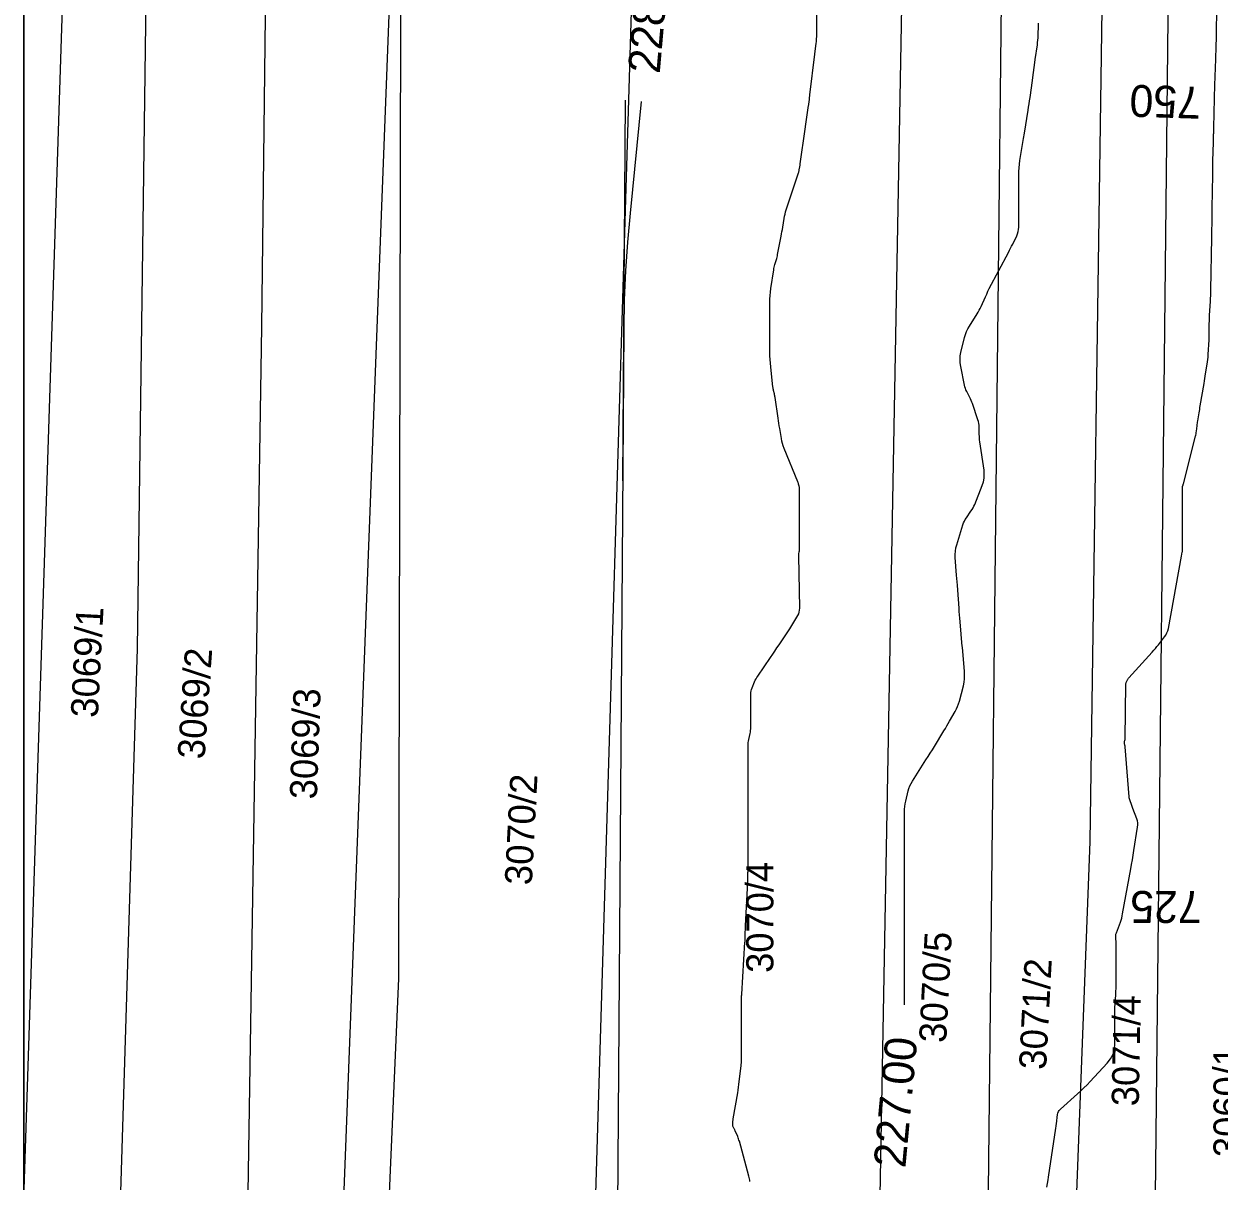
# Model space of a CAD drawing. Extents: x -534410 to -534262, y -1190162 to -1189584.
# Drawn here: x -534410.13 to -534372.7, y -1189864.58 to -1189828.34 of the extents above; entities that cross this region are included whole.
import ezdxf

# ---------------------------------------------------------------- set-up
doc = ezdxf.new("R2010")
doc.units = 0
for name, color, linetype in [('30', 7, 'Continuous'), ('31', 7, 'Continuous'), ('40', 7, 'Continuous'), ('_N_text', 7, 'Continuous'), ('_rámeček', 7, 'Continuous'), ('_rámeček_mřížka', 7, 'Continuous'), ('Hranice parcel', 7, 'Continuous'), ('Parcelní čísla', 7, 'Continuous')]:
    doc.layers.add(name, color=color, linetype=linetype)

msp = doc.modelspace()

# ---------------------------------------------------------------- linework, layer by layer
at = {"layer": '30'}
for points in [[(-534382.549, -1189859.059), (-534382.549, -1189853.012), (-534382.547, -1189852.928), (-534382.54, -1189852.846), (-534382.527, -1189852.764), (-534382.51, -1189852.682), (-534382.432, -1189852.357), (-534382.409, -1189852.278), (-534382.38, -1189852.2), (-534382.345, -1189852.126), (-534382.303, -1189852.054), (-534381.877, -1189851.384), (-534381.81, -1189851.279), (-534381.744, -1189851.173), (-534381.678, -1189851.068), (-534381.613, -1189850.961), (-534381.314, -1189850.474), (-534381.269, -1189850.399), (-534381.224, -1189850.323), (-534381.179, -1189850.247), (-534381.136, -1189850.171), (-534380.961, -1189849.866), (-534380.921, -1189849.788), (-534380.885, -1189849.709), (-534380.855, -1189849.627), (-534380.831, -1189849.543), (-534380.707, -1189849.062), (-534380.684, -1189848.953), (-534380.67, -1189848.843), (-534380.666, -1189848.732), (-534380.671, -1189848.621), (-534380.738, -1189847.85), (-534380.739, -1189847.838), (-534380.807, -1189847.058), (-534380.816, -1189846.951), (-534380.825, -1189846.844), (-534380.834, -1189846.738), (-534380.842, -1189846.631), (-534380.883, -1189846.069), (-534380.895, -1189845.912), (-534380.918, -1189845.597), (-534380.958, -1189845.052), (-534380.961, -1189844.949), (-534380.954, -1189844.847), (-534380.938, -1189844.745), (-534380.912, -1189844.645), (-534380.721, -1189844.021), (-534380.701, -1189843.963), (-534380.676, -1189843.907), (-534380.647, -1189843.853), (-534380.613, -1189843.802), (-534380.469, -1189843.6), (-534380.435, -1189843.548), (-534380.404, -1189843.495), (-534380.376, -1189843.44), (-534380.351, -1189843.383), (-534380.117, -1189842.797), (-534380.079, -1189842.679), (-534380.056, -1189842.56), (-534380.05, -1189842.438), (-534380.06, -1189842.314), (-534380.189, -1189841.421), (-534380.196, -1189841.364), (-534380.202, -1189841.306), (-534380.206, -1189841.249), (-534380.208, -1189841.191), (-534380.213, -1189840.96), (-534380.216, -1189840.903), (-534380.224, -1189840.846), (-534380.236, -1189840.79), (-534380.252, -1189840.735), (-534380.425, -1189840.228), (-534380.443, -1189840.178), (-534380.463, -1189840.13), (-534380.484, -1189840.082), (-534380.507, -1189840.034), (-534380.603, -1189839.846), (-534380.625, -1189839.799), (-534380.644, -1189839.75), (-534380.66, -1189839.7), (-534380.672, -1189839.649), (-534380.79, -1189839.066), (-534380.806, -1189838.955), (-534380.81, -1189838.845), (-534380.802, -1189838.735), (-534380.782, -1189838.625), (-534380.669, -1189838.154), (-534380.642, -1189838.061), (-534380.608, -1189837.971), (-534380.567, -1189837.884), (-534380.518, -1189837.8), (-534380.273, -1189837.414), (-534380.24, -1189837.36), (-534380.209, -1189837.305), (-534380.179, -1189837.248), (-534380.151, -1189837.191), (-534380.011, -1189836.888), (-534380.001, -1189836.866), (-534379.991, -1189836.844), (-534379.982, -1189836.822), (-534379.973, -1189836.8), (-534379.938, -1189836.711), (-534379.929, -1189836.689), (-534379.92, -1189836.667), (-534379.909, -1189836.646), (-534379.898, -1189836.625), (-534379.293, -1189835.49), (-534379.259, -1189835.426), (-534379.226, -1189835.362), (-534379.194, -1189835.298), (-534379.162, -1189835.233), (-534379.036, -1189834.974), (-534379.008, -1189834.908), (-534378.989, -1189834.841), (-534378.977, -1189834.772), (-534378.973, -1189834.7), (-534378.973, -1189833.078), (-534378.971, -1189832.961), (-534378.964, -1189832.845), (-534378.952, -1189832.73), (-534378.935, -1189832.614), (-534378.822, -1189831.924), (-534378.794, -1189831.754), (-534378.678, -1189831.042), (-534378.662, -1189830.943), (-534378.647, -1189830.844), (-534378.632, -1189830.745), (-534378.618, -1189830.646), (-534378.544, -1189830.112), (-534378.52, -1189829.931), (-534378.478, -1189829.631), (-534378.453, -1189829.451), (-534378.39, -1189828.995), (-534378.381, -1189828.919), (-534378.374, -1189828.844), (-534378.368, -1189828.769), (-534378.364, -1189828.693), (-534378.354, -1189828.39), (-534378.352, -1189828.315)], [(-534390.792, -1189830.764), (-534391.145, -1189834.263), (-534391.226, -1189835.167), (-534391.285, -1189836.071), (-534391.324, -1189836.977), (-534391.341, -1189837.885), (-534391.562, -1189868.34)]]:
    msp.add_lwpolyline(points, dxfattribs=at)
at = {"layer": '31'}
for points in [[(-534387.392, -1189864.586), (-534387.396, -1189864.543), (-534387.403, -1189864.501), (-534387.411, -1189864.459), (-534387.422, -1189864.417), (-534387.722, -1189863.328), (-534387.733, -1189863.291), (-534387.746, -1189863.254), (-534387.759, -1189863.217), (-534387.774, -1189863.182), (-534387.852, -1189862.999), (-534387.859, -1189862.984), (-534387.867, -1189862.968), (-534387.874, -1189862.952), (-534387.882, -1189862.937), (-534387.915, -1189862.875), (-534387.922, -1189862.86), (-534387.927, -1189862.844), (-534387.929, -1189862.827), (-534387.929, -1189862.81), (-534387.922, -1189862.712), (-534387.921, -1189862.69), (-534387.918, -1189862.668), (-534387.915, -1189862.646), (-534387.912, -1189862.625), (-534387.773, -1189861.813), (-534387.759, -1189861.724), (-534387.746, -1189861.636), (-534387.734, -1189861.548), (-534387.723, -1189861.459), (-534387.666, -1189860.969), (-534387.664, -1189860.948), (-534387.662, -1189860.926), (-534387.66, -1189860.904), (-534387.659, -1189860.883), (-534387.654, -1189860.796), (-534387.653, -1189860.774), (-534387.652, -1189860.753), (-534387.652, -1189860.731), (-534387.651, -1189860.709), (-534387.651, -1189858.867), (-534387.651, -1189858.856), (-534387.651, -1189858.845), (-534387.651, -1189858.833), (-534387.651, -1189858.822), (-534387.649, -1189858.773), (-534387.649, -1189858.762), (-534387.648, -1189858.75), (-534387.648, -1189858.738), (-534387.647, -1189858.726), (-534387.545, -1189857.096), (-534387.544, -1189857.071), (-534387.542, -1189857.045), (-534387.541, -1189857.02), (-534387.541, -1189856.995), (-534387.537, -1189856.895), (-534387.536, -1189856.844), (-534387.535, -1189856.794), (-534387.532, -1189856.685), (-534387.531, -1189856.659), (-534387.53, -1189856.632), (-534387.529, -1189856.605), (-534387.528, -1189856.579), (-534387.46, -1189855.203), (-534387.458, -1189855.167), (-534387.457, -1189855.131), (-534387.456, -1189855.095), (-534387.455, -1189855.06), (-534387.451, -1189854.916), (-534387.45, -1189854.88), (-534387.45, -1189854.844), (-534387.45, -1189854.809), (-534387.449, -1189854.773), (-534387.449, -1189850.942), (-534387.448, -1189850.893), (-534387.444, -1189850.845), (-534387.437, -1189850.797), (-534387.428, -1189850.749), (-534387.385, -1189850.559), (-534387.375, -1189850.512), (-534387.368, -1189850.464), (-534387.364, -1189850.415), (-534387.363, -1189850.367), (-534387.363, -1189849.328), (-534387.36, -1189849.277), (-534387.353, -1189849.227), (-534387.34, -1189849.178), (-534387.323, -1189849.13), (-534387.243, -1189848.94), (-534387.222, -1189848.893), (-534387.199, -1189848.847), (-534387.173, -1189848.803), (-534387.145, -1189848.759), (-534386.746, -1189848.177), (-534386.678, -1189848.077), (-534386.61, -1189847.978), (-534386.543, -1189847.878), (-534386.476, -1189847.778), (-534386.142, -1189847.277), (-534386.109, -1189847.226), (-534386.076, -1189847.175), (-534386.045, -1189847.124), (-534386.013, -1189847.072), (-534385.89, -1189846.863), (-534385.864, -1189846.81), (-534385.845, -1189846.755), (-534385.834, -1189846.697), (-534385.831, -1189846.638), (-534385.861, -1189844.993), (-534385.861, -1189844.978), (-534385.86, -1189844.963), (-534385.859, -1189844.948), (-534385.857, -1189844.933), (-534385.846, -1189844.874), (-534385.844, -1189844.859), (-534385.842, -1189844.844), (-534385.842, -1189844.829), (-534385.841, -1189844.814), (-534385.841, -1189842.879), (-534385.842, -1189842.862), (-534385.843, -1189842.845), (-534385.846, -1189842.828), (-534385.85, -1189842.812), (-534385.867, -1189842.746), (-534385.871, -1189842.729), (-534385.876, -1189842.713), (-534385.882, -1189842.697), (-534385.888, -1189842.681), (-534386.317, -1189841.629), (-534386.345, -1189841.553), (-534386.37, -1189841.477), (-534386.389, -1189841.4), (-534386.405, -1189841.321), (-534386.459, -1189841.003), (-534386.472, -1189840.924), (-534386.485, -1189840.844), (-534386.497, -1189840.765), (-534386.508, -1189840.685), (-534386.601, -1189840.033), (-534386.606, -1189840.006), (-534386.611, -1189839.979), (-534386.616, -1189839.952), (-534386.622, -1189839.925), (-534386.649, -1189839.818), (-534386.656, -1189839.791), (-534386.661, -1189839.764), (-534386.665, -1189839.737), (-534386.669, -1189839.709), (-534386.739, -1189839.074), (-534386.75, -1189838.959), (-534386.758, -1189838.844), (-534386.763, -1189838.729), (-534386.765, -1189838.613), (-534386.765, -1189838.111), (-534386.765, -1189837.866), (-534386.765, -1189837.621), (-534386.765, -1189837.069), (-534386.763, -1189836.957), (-534386.756, -1189836.845), (-534386.746, -1189836.733), (-534386.732, -1189836.622), (-534386.645, -1189836.036), (-534386.638, -1189835.996), (-534386.63, -1189835.956), (-534386.62, -1189835.916), (-534386.609, -1189835.876), (-534386.562, -1189835.719), (-534386.551, -1189835.68), (-534386.541, -1189835.64), (-534386.532, -1189835.6), (-534386.524, -1189835.56), (-534386.412, -1189834.982), (-534386.399, -1189834.913), (-534386.387, -1189834.844), (-534386.375, -1189834.775), (-534386.363, -1189834.706), (-534386.318, -1189834.43), (-534386.306, -1189834.361), (-534386.291, -1189834.293), (-534386.273, -1189834.226), (-534386.252, -1189834.159), (-534385.87, -1189833.002), (-534385.863, -1189832.979), (-534385.857, -1189832.956), (-534385.851, -1189832.933), (-534385.847, -1189832.909), (-534385.83, -1189832.814), (-534385.826, -1189832.79), (-534385.822, -1189832.766), (-534385.818, -1189832.742), (-534385.815, -1189832.718), (-534385.763, -1189832.348), (-534385.753, -1189832.278), (-534385.743, -1189832.209), (-534385.733, -1189832.139), (-534385.723, -1189832.069), (-534385.573, -1189831.039), (-534385.551, -1189830.888), (-534385.548, -1189830.866), (-534385.545, -1189830.844), (-534385.542, -1189830.823), (-534385.54, -1189830.801), (-534385.51, -1189830.562), (-534385.354, -1189829.289), (-534385.312, -1189828.943), (-534385.307, -1189828.894), (-534385.303, -1189828.844), (-534385.301, -1189828.795), (-534385.3, -1189828.745), (-534385.3, -1189820.955)], [(-534378.088, -1189864.767), (-534378.053, -1189864.535), (-534378.041, -1189864.457), (-534377.811, -1189862.919), (-534377.802, -1189862.857), (-534377.799, -1189862.838), (-534377.792, -1189862.782), (-534377.756, -1189862.493), (-534377.745, -1189862.445), (-534377.727, -1189862.401), (-534377.702, -1189862.361), (-534377.668, -1189862.326), (-534377.131, -1189861.844), (-534377.03, -1189861.751), (-534376.931, -1189861.656), (-534376.834, -1189861.559), (-534376.74, -1189861.46), (-534376.201, -1189860.886), (-534376.095, -1189860.751), (-534376.02, -1189860.604), (-534375.974, -1189860.445), (-534375.959, -1189860.275), (-534375.959, -1189859.161), (-534375.959, -1189859.111), (-534375.957, -1189859.061), (-534375.955, -1189859.011), (-534375.951, -1189858.961), (-534375.935, -1189858.761), (-534375.931, -1189858.711), (-534375.928, -1189858.661), (-534375.927, -1189858.611), (-534375.926, -1189858.561), (-534375.926, -1189857.074), (-534375.926, -1189857.051), (-534375.927, -1189857.028), (-534375.927, -1189857.005), (-534375.928, -1189856.982), (-534375.931, -1189856.89), (-534375.93, -1189856.868), (-534375.928, -1189856.845), (-534375.923, -1189856.823), (-534375.916, -1189856.802), (-534375.79, -1189856.466), (-534375.768, -1189856.402), (-534375.749, -1189856.338), (-534375.733, -1189856.273), (-534375.719, -1189856.207), (-534375.464, -1189854.801), (-534375.439, -1189854.657), (-534375.414, -1189854.513), (-534375.39, -1189854.369), (-534375.367, -1189854.224), (-534375.252, -1189853.491), (-534375.246, -1189853.424), (-534375.248, -1189853.358), (-534375.258, -1189853.293), (-534375.277, -1189853.229), (-534375.395, -1189852.904), (-534375.406, -1189852.874), (-534375.417, -1189852.845), (-534375.428, -1189852.815), (-534375.439, -1189852.786), (-534375.485, -1189852.668), (-534375.496, -1189852.639), (-534375.504, -1189852.609), (-534375.51, -1189852.578), (-534375.513, -1189852.547), (-534375.639, -1189850.973), (-534375.64, -1189850.96), (-534375.642, -1189850.947), (-534375.645, -1189850.934), (-534375.648, -1189850.921), (-534375.66, -1189850.87), (-534375.663, -1189850.857), (-534375.663, -1189850.845), (-534375.662, -1189850.832), (-534375.66, -1189850.819), (-534375.646, -1189850.767), (-534375.643, -1189850.754), (-534375.641, -1189850.74), (-534375.64, -1189850.727), (-534375.639, -1189850.714), (-534375.615, -1189849.009), (-534375.614, -1189848.991), (-534375.61, -1189848.974), (-534375.605, -1189848.957), (-534375.598, -1189848.941), (-534375.564, -1189848.877), (-534375.555, -1189848.861), (-534375.545, -1189848.846), (-534375.534, -1189848.831), (-534375.522, -1189848.818), (-534374.792, -1189848.011), (-534374.741, -1189847.954), (-534374.692, -1189847.896), (-534374.643, -1189847.837), (-534374.596, -1189847.778), (-534374.408, -1189847.536), (-534374.366, -1189847.474), (-534374.331, -1189847.408), (-534374.305, -1189847.339), (-534374.287, -1189847.266), (-534373.874, -1189845.001), (-534373.863, -1189844.939), (-534373.851, -1189844.876), (-534373.849, -1189844.86), (-534373.847, -1189844.844), (-534373.846, -1189844.829), (-534373.845, -1189844.813), (-534373.845, -1189842.865), (-534373.845, -1189842.855), (-534373.844, -1189842.845), (-534373.842, -1189842.834), (-534373.84, -1189842.824), (-534373.826, -1189842.774), (-534373.821, -1189842.754), (-534373.818, -1189842.744), (-534373.436, -1189841.252), (-534373.426, -1189841.212), (-534373.418, -1189841.172), (-534373.411, -1189841.131), (-534373.406, -1189841.09), (-534373.387, -1189840.926), (-534373.382, -1189840.886), (-534373.377, -1189840.845), (-534373.371, -1189840.804), (-534373.365, -1189840.763), (-534373.324, -1189840.517), (-534373.315, -1189840.462), (-534373.306, -1189840.408), (-534373.297, -1189840.353), (-534373.288, -1189840.298), (-534373.169, -1189839.594), (-534373.156, -1189839.519), (-534373.144, -1189839.444), (-534373.131, -1189839.369), (-534373.119, -1189839.294), (-534373.071, -1189838.994), (-534373.059, -1189838.919), (-534373.05, -1189838.844), (-534373.043, -1189838.769), (-534373.038, -1189838.693), (-534373.011, -1189838.235), (-534373.008, -1189838.17), (-534373.006, -1189838.105), (-534373.004, -1189838.04), (-534373.004, -1189837.975), (-534373.004, -1189837.714), (-534373.003, -1189837.649), (-534373.002, -1189837.584), (-534372.999, -1189837.519), (-534372.996, -1189837.454), (-534372.968, -1189837.029), (-534372.963, -1189836.937), (-534372.959, -1189836.844), (-534372.955, -1189836.752), (-534372.954, -1189836.659), (-534372.946, -1189836.144), (-534372.945, -1189836.095), (-534372.944, -1189836.046), (-534372.943, -1189835.997), (-534372.942, -1189835.948), (-534372.936, -1189835.752), (-534372.935, -1189835.703), (-534372.934, -1189835.654), (-534372.933, -1189835.605), (-534372.932, -1189835.556), (-534372.925, -1189835.047), (-534372.924, -1189834.946), (-534372.923, -1189834.844), (-534372.921, -1189834.743), (-534372.92, -1189834.642), (-534372.914, -1189834.097), (-534372.913, -1189834.056), (-534372.912, -1189834.014), (-534372.912, -1189833.973), (-534372.911, -1189833.931), (-534372.907, -1189833.765), (-534372.906, -1189833.724), (-534372.905, -1189833.683), (-534372.905, -1189833.641), (-534372.904, -1189833.6), (-534372.898, -1189833.054), (-534372.896, -1189832.949), (-534372.895, -1189832.845), (-534372.893, -1189832.74), (-534372.891, -1189832.635), (-534372.878, -1189832.042), (-534372.877, -1189832.01), (-534372.876, -1189831.978), (-534372.875, -1189831.945), (-534372.874, -1189831.913), (-534372.869, -1189831.785), (-534372.868, -1189831.753), (-534372.867, -1189831.721), (-534372.866, -1189831.689), (-534372.865, -1189831.657), (-534372.852, -1189831.064), (-534372.85, -1189830.954), (-534372.847, -1189830.845), (-534372.844, -1189830.735), (-534372.841, -1189830.625), (-534372.82, -1189829.956), (-534372.819, -1189829.938), (-534372.818, -1189829.92), (-534372.818, -1189829.902), (-534372.817, -1189829.884), (-534372.813, -1189829.813), (-534372.812, -1189829.795), (-534372.811, -1189829.777), (-534372.81, -1189829.759), (-534372.81, -1189829.741), (-534372.79, -1189829.078), (-534372.787, -1189828.961), (-534372.784, -1189828.844), (-534372.782, -1189828.728), (-534372.78, -1189828.611), (-534372.773, -1189827.888)], [(-534391.375, -1189842.65), (-534391.289, -1189830.721)]]:
    msp.add_lwpolyline(points, dxfattribs=at)
at = {"layer": '_rámeček'}
msp.add_line((-534410.126, -1189584.47), (-534410.126, -1190161.97), dxfattribs=at)
msp.add_lwpolyline([(-534410.126, -1189794.47), (-534261.626, -1189794.47), (-534261.626, -1189899.47), (-534410.126, -1189899.47)], close=True, dxfattribs=at)
at = {"layer": '_rámeček_mřížka'}
msp.add_line((-534410.126, -1189584.47), (-534410.126, -1190161.97), dxfattribs=at)
at = {"layer": 'Hranice parcel'}
for p, q in [((-534410.126, -1189865.16), (-534408.06, -1189801.17)), ((-534403.19, -1189945.91), (-534398.3, -1189817.87))]:
    msp.add_line(p, q, dxfattribs=at)
for points in [[(-534395.93, -1189955.06), (-534393.76, -1189916.2), (-534389.49, -1189774.63), (-534390.92, -1189749.37)], [(-534385.61, -1189919.11), (-534380.06, -1189877.29), (-534378.67, -1189750.28)], [(-534385.61, -1189919.11), (-534383.81, -1189892.54), (-534382.22, -1189804.86), (-534381.85, -1189775.86), (-534383.09, -1189750.44)], [(-534383.94, -1189956.8), (-534379.19, -1189918.48), (-534376.74, -1189853.94), (-534375.92, -1189797.44), (-534376.41, -1189774.02), (-534378.12, -1189750.26)], [(-534406.13, -1189942), (-534403.45, -1189886.77), (-534402.68, -1189837.82), (-534401.95, -1189776.76), (-534406.3, -1189754), (-534406.48, -1189752.31)], [(-534373.61, -1189764.09), (-534375.04, -1189897.07), (-534384.28, -1189963.65)], [(-534410.126, -1189932.794), (-534408.16, -1189899.66), (-534406.57, -1189847.9), (-534405.68, -1189781.38), (-534406.95, -1189766.9)], [(-534403.19, -1189945.91), (-534400.52, -1189907.49), (-534398.39, -1189858.23), (-534398.3, -1189817.87)]]:
    msp.add_lwpolyline(points, dxfattribs=at)

# ---------------------------------------------------------------- texts
at = {"layer": '40'}
for s, rotation, p in [('228.00', 85.0301, (-534390.216, -1189829.913)), ('227.00', 84.6806, (-534382.524, -1189864.186))]:
    msp.add_text(s, height=1, rotation=rotation, dxfattribs=at).set_placement(p)
at = {"layer": '_N_text'}
for s, rotation, p in [('750', 178.2276, (-534373.254, -1189830.308)), ('725', 179.8487, (-534373.247, -1189855.495))]:
    msp.add_text(s, height=1, rotation=rotation, dxfattribs=at).set_placement(p)
at = {"layer": 'Parcelní čísla'}
for s, rotation, p in [('3069/1', 87, (-534407.812, -1189850.078)), ('3069/2', 86, (-534404.47, -1189851.381)), ('3069/3', 88, (-534400.953, -1189852.63)), ('3070/2', 87, (-534394.222, -1189855.322)), ('3070/4', 90, (-534386.656, -1189858.055)), ('3070/5', 87, (-534381.247, -1189860.26)), ('3071/2', 87, (-534378.118, -1189861.101)), ('3071/4', 89, (-534375.214, -1189862.236)), ('3060/1', 90, (-534372.025, -1189863.823))]:
    msp.add_text(s, height=0.85, rotation=rotation, dxfattribs=at).set_placement(p)

doc.saveas('drawing.dxf')
